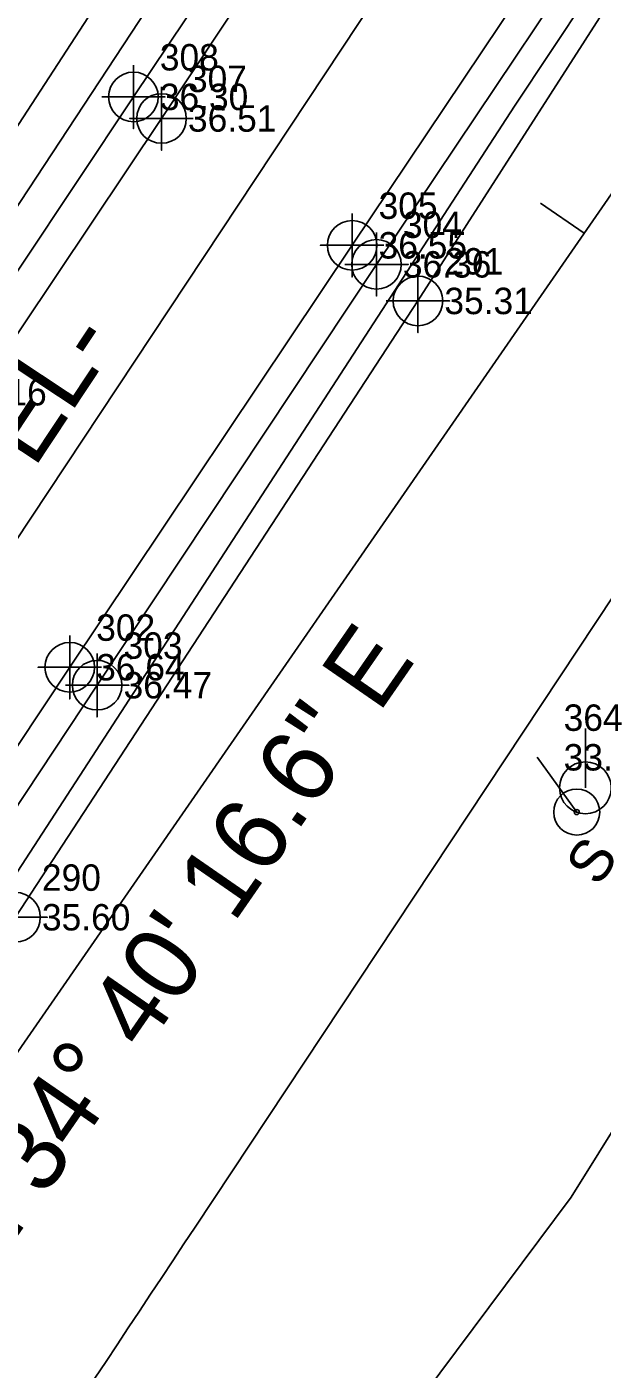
# Model space of a CAD drawing. Extents: x 2603627 to 2605187, y 896619 to 899063.
# Drawn here: x 2604707.2 to 2604761.6, y 898327.7 to 898454.7 of the extents above; entities that cross this region are included whole.
import ezdxf

# ---------------------------------------------------------------- set-up
doc = ezdxf.new("R2010")
doc.units = 0
for name, color, linetype in [('Exist Horizontal Alignment', 7, 'Continuous'), ('Exist Horizontal Alignment Direction Label', 7, 'Continuous'), ('Exist Horizontal Baseline Alignment', 7, 'Continuous'), ('Exist Horizontal Baseline Alignment Direction Label', 7, 'Continuous'), ('Exist Horizontal Baseline Alignment Tick small', 7, 'Continuous'), ('Exist Other Culture Sign CELL', 7, 'Continuous'), ('Exist Other Culture Sign Cogo Elevation', 7, 'Continuous'), ('Exist Other Culture Sign Cogo Number', 7, 'Continuous'), ('Exist Other Culture Sign Text', 7, 'Continuous'), ('Exist Right of Way Line', 7, 'Continuous'), ('Exist Roads EOP', 7, 'Continuous'), ('Exist Roads EOP Cogo Elevation', 7, 'Continuous'), ('Exist Roads EOP Cogo Number', 7, 'Continuous'), ('Exist Roads EOP Cogo Point CELL', 7, 'Continuous'), ('Exist Roads EOT', 7, 'Continuous'), ('Exist Roads EOT Cogo Elevation', 7, 'Continuous'), ('Exist Roads EOT Cogo Number', 7, 'Continuous'), ('Exist Roads EOT Cogo Point CELL', 7, 'Continuous'), ('Exist Roads Soil Cogo Elevation', 7, 'Continuous'), ('Exist Utilities Power Pole CELL', 7, 'Continuous'), ('Exist Utilities Telephone UG Cable SUE LOS C', 7, 'Continuous'), ('Exist Utilities Telephone UG FO SUE LOS C', 7, 'Continuous'), ('Exist Utilities Water UG Line SUE LOS B', 7, 'Continuous'), ('Exist Utilities Water UG Line SUE LOS B Cogo Elevation', 7, 'Continuous'), ('Exist Utilities Water UG Line SUE LOS B Cogo Number', 7, 'Continuous'), ('Exist Utilities Water UG Line SUE LOS B Cogo Point CELL', 7, 'Continuous'), ('Exist Vegetation Woods Line', 7, 'Continuous')]:
    doc.layers.add(name, color=color, linetype=linetype)

# ---------------------------------------------------------------- blocks, each defined once
blk = doc.blocks.new('EXIST UTILITIES WATER UG LINE SUE LOS B COGO POINT')
at = {"layer": 'Exist Utilities Water UG Line SUE LOS B Cogo Point CELL'}
blk.add_lwpolyline([(0, 0.06), (0, -0.06), (0, 0), (0.06, 0), (-0.06, 0)], dxfattribs=at)
blk.add_circle((0, 0), 0.0469, dxfattribs=at)
blk = doc.blocks.new('EXIST ROADS EOT COGO POINT')
at = {"layer": 'Exist Roads EOT Cogo Point CELL'}
blk.add_lwpolyline([(0, 0.06), (0, -0.06), (0, 0), (-0.06, 0), (0.06, 0)], dxfattribs=at)
blk.add_circle((0, 0), 0.0469, dxfattribs=at)
blk = doc.blocks.new('EXIST ROADS EOP COGO POINT')
at = {"layer": 'Exist Roads EOP Cogo Point CELL'}
blk.add_lwpolyline([(0, 0.06), (0, -0.06), (0, 0), (0.06, 0), (-0.06, 0)], dxfattribs=at)
blk.add_circle((0, 0), 0.0469, dxfattribs=at)
blk = doc.blocks.new('EXIST OTHER CULTURE SIGN')
at = {"layer": 'Exist Other Culture Sign CELL'}
for radius in [0.0436, 0.0048]:
    blk.add_circle((0, 0), radius, dxfattribs=at)

msp = doc.modelspace()

# ---------------------------------------------------------------- linework, layer by layer
at = {"layer": 'Exist Horizontal Alignment'}
msp.add_line((2604681.44, 898368.79), (2605041.11, 898911.74), dxfattribs=at)
at = {"layer": 'Exist Horizontal Baseline Alignment'}
msp.add_line((2604544.96, 898124.44), (2604793.6, 898483.9), dxfattribs=at)
at = {"layer": 'Exist Horizontal Baseline Alignment Tick small'}
msp.add_line((2604759.91, 898435.2), (2604755.8, 898438.05), dxfattribs=at)
at = {"layer": 'Exist Other Culture Sign CELL'}
msp.add_line((2604755.48, 898385.62), (2604759.22, 898380.44), dxfattribs=at)
at = {"layer": 'Exist Right of Way Line'}
msp.add_line((2604723.13, 898341.18), (2605082.79, 898884.13), dxfattribs=at)
msp.add_arc((2687215.61, 843696.03), 98950, 146.4784826, 146.513795, dxfattribs=at)
at = {"layer": 'Exist Roads EOP'}
msp.add_line((2604685.97, 898350.32), (2604713.86, 898392.44), dxfattribs=at)
for points in [[(2604577.96, 898237.27), (2604606.45, 898281.24), (2604633.89, 898322.5), (2604662.45, 898365.47), (2604690.62, 898408.06), (2604717.29, 898448.09), (2604745.46, 898490.11), (2604773.6, 898532.6), (2604800.88, 898573.95), (2604828.34, 898615.46), (2604855.1, 898656.15), (2604883.53, 898699.09), (2604911.29, 898740.95), (2604939.38, 898783.41), (2604966.33, 898824.04), (2604993.38, 898865.27), (2605022.2, 898908.38), (2605029.46, 898919.46)], [(2604713.86, 898392.44), (2604740.28, 898432.25), (2604768.45, 898474.26), (2604797.27, 898517.92), (2604823.93, 898558.47), (2604851.31, 898599.84), (2604878.52, 898641.09), (2604906.84, 898683.65), (2604934.68, 898725.71), (2604962.63, 898767.92), (2604989.32, 898808.49), (2605016.42, 898849.59), (2605045.34, 898893.33), (2605052.55, 898904.16)]]:
    msp.add_lwpolyline(points, dxfattribs=at)
at = {"layer": 'Exist Roads EOT'}
for points in [[(2604580.65, 898235.67), (2604609.23, 898279.3), (2604636.66, 898320.72), (2604665.18, 898363.91), (2604693.37, 898406.36), (2604719.95, 898446.05), (2604748, 898488.34), (2604776.15, 898530.84), (2604803.5, 898572.3), (2604830.95, 898613.91), (2604857.58, 898654.47), (2604886.02, 898697.38), (2604913.86, 898739.33), (2604942.03, 898781.72), (2604969.06, 898822.38), (2604996.07, 898863.44), (2605024.73, 898906.73), (2605032, 898917.78)], [(2604598.04, 898223.4), (2604627.23, 898267.23), (2604654.64, 898308.57), (2604683.28, 898352.01), (2604711.27, 898394.14), (2604737.98, 898434.05), (2604766.04, 898475.94), (2604794.96, 898519.26), (2604821.61, 898559.82), (2604848.89, 898601.4), (2604876.12, 898642.73), (2604904.4, 898685.35), (2604932.33, 898727.23), (2604960.29, 898769.49), (2604987.32, 898810.19), (2605014.12, 898850.95), (2605043.08, 898894.89), (2605050.2, 898905.72)]]:
    msp.add_lwpolyline(points, dxfattribs=at)
at = {"layer": 'Exist Utilities Power Pole CELL'}
for q in [(2604760.04, 898388.36), (2604760.04, 898382.73)]:
    msp.add_line((2604760.04, 898382.73), q, dxfattribs=at)
msp.add_circle((2604760.04, 898382.73), 2.45, dxfattribs=at)
at = {"layer": 'Exist Utilities Telephone UG Cable SUE LOS C'}
for p, q in [((2604753.32, 898447.21), (2604850.74, 898593.69)), ((2604580.04, 898245.37), (2604795.48, 898573.63)), ((2604698.64, 898362.97), (2604753.32, 898447.21))]:
    msp.add_line(p, q, dxfattribs=at)
at = {"layer": 'Exist Utilities Telephone UG FO SUE LOS C'}
msp.add_line((2604676.14, 898398.98), (2605019.3, 898926.2), dxfattribs=at)
at = {"layer": 'Exist Utilities Water UG Line SUE LOS B'}
msp.add_lwpolyline([(2604590.41, 898183.07), (2604608.13, 898210.78), (2604631.33, 898247.72), (2604631.98, 898248.77), (2604637.93, 898260.9), (2604650.01, 898281.75), (2604670.13, 898312.66), (2604706.14, 898370.49), (2604744.2, 898428.79), (2604775.85, 898478.14), (2604817.62, 898541.22), (2604844.76, 898580.18), (2604876.2, 898627.22), (2604907.55, 898675.15), (2604931.69, 898711.47), (2604963.51, 898758.63), (2604991.08, 898800.9), (2605022.23, 898847.26), (2605044.13, 898880.13), (2605057.71, 898900.74)], dxfattribs=at)
at = {"layer": 'Exist Vegetation Woods Line'}
msp.add_lwpolyline([(2604653.24, 898142.95), (2604632.09, 898155.82), (2604674.87, 898231.68), (2604758.69, 898344.01), (2604864.62, 898513.8)], dxfattribs=at)

# ---------------------------------------------------------------- block references
at = {"layer": 'Exist Other Culture Sign CELL', "xscale": 50, "yscale": 50}
msp.add_blockref('EXIST OTHER CULTURE SIGN', (2604759.22, 898380.44), dxfattribs=at)
at = {"layer": 'Exist Roads EOP Cogo Point CELL', "xscale": 50, "yscale": 50}
for p in [(2604717.29, 898448.09), (2604740.28, 898432.25), (2604713.86, 898392.44)]:
    msp.add_blockref('EXIST ROADS EOP COGO POINT', p, dxfattribs=at)
at = {"layer": 'Exist Roads EOT Cogo Point CELL', "xscale": 50, "yscale": 50}
for p in [(2604719.95, 898446.05), (2604737.98, 898434.05), (2604711.27, 898394.14)]:
    msp.add_blockref('EXIST ROADS EOT COGO POINT', p, dxfattribs=at)
at = {"layer": 'Exist Utilities Water UG Line SUE LOS B Cogo Point CELL', "xscale": 50, "yscale": 50}
for p in [(2604744.2, 898428.79), (2604706.14, 898370.49)]:
    msp.add_blockref('EXIST UTILITIES WATER UG LINE SUE LOS B COGO POINT', p, dxfattribs=at)

# ---------------------------------------------------------------- texts
at = {"layer": 'Exist Horizontal Alignment Direction Label'}
msp.add_text('-EL-', height=7, rotation=56.4785, dxfattribs=at).set_placement((2604706.16, 898410.25))
at = {"layer": 'Exist Horizontal Baseline Alignment Direction Label'}
msp.add_text('N 34%%d 40\' 16.6" E', height=7, rotation=55.3287, dxfattribs=at).set_placement((2604703.48, 898336.18))
at = {"layer": 'Exist Other Culture Sign Cogo Elevation'}
msp.add_text('33.14', height=2.5, dxfattribs=at).set_placement((2604757.98, 898384.37))
at = {"layer": 'Exist Other Culture Sign Cogo Number'}
msp.add_text('364', height=2.5, dxfattribs=at).set_placement((2604757.98, 898388.12))
at = {"layer": 'Exist Other Culture Sign Text'}
msp.add_text('S', height=4, rotation=56.4094, dxfattribs=at).set_placement((2604761.29, 898373.27))
at = {"layer": 'Exist Roads EOP Cogo Elevation'}
for s, p in [('36.30', (2604719.79, 898446.84)), ('36.36', (2604742.78, 898431)), ('36.47', (2604716.36, 898391.19))]:
    msp.add_text(s, height=2.5, dxfattribs=at).set_placement(p)
at = {"layer": 'Exist Roads EOP Cogo Number'}
for s, p in [('308', (2604719.79, 898450.59)), ('304', (2604742.78, 898434.75)), ('303', (2604716.36, 898394.94))]:
    msp.add_text(s, height=2.5, dxfattribs=at).set_placement(p)
at = {"layer": 'Exist Roads EOT Cogo Elevation'}
for s, p in [('36.51', (2604722.45, 898444.8)), ('36.55', (2604740.48, 898432.8)), ('36.64', (2604713.77, 898392.89))]:
    msp.add_text(s, height=2.5, dxfattribs=at).set_placement(p)
at = {"layer": 'Exist Roads EOT Cogo Number'}
for s, p in [('307', (2604722.45, 898448.55)), ('305', (2604740.48, 898436.55)), ('302', (2604713.77, 898396.64))]:
    msp.add_text(s, height=2.5, dxfattribs=at).set_placement(p)
at = {"layer": 'Exist Roads Soil Cogo Elevation'}
msp.add_text('36.16', height=2.5, dxfattribs=at).set_placement((2604700.73, 898418.9))
at = {"layer": 'Exist Utilities Water UG Line SUE LOS B Cogo Elevation'}
for s, p in [('35.31', (2604746.7, 898427.54)), ('35.60', (2604708.64, 898369.24))]:
    msp.add_text(s, height=2.5, dxfattribs=at).set_placement(p)
at = {"layer": 'Exist Utilities Water UG Line SUE LOS B Cogo Number'}
for s, p in [('291', (2604746.7, 898431.29)), ('290', (2604708.64, 898372.99))]:
    msp.add_text(s, height=2.5, dxfattribs=at).set_placement(p)

doc.saveas('drawing.dxf')
